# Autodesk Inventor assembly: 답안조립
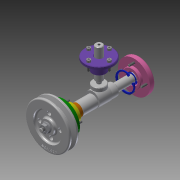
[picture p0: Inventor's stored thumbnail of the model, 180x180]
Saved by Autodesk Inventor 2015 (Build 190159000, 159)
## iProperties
Created: 2020-08
Part Number: 답안조립
Document SubType Name: Assembly
Designer: now
Author: now
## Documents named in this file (18)
- C:\Users\now\Desktop\700806V1042\답안조립.iam
- C:\Users\now\Desktop\700806V1042\Ű 3x3x12.ipt
- C:\Users\now\Desktop\700806V1042\V-벨트풀리.ipt
- C:\Users\now\Desktop\700806V1042\너트 M8.ipt
- C:\Users\now\Desktop\700806V1042\답안본체.ipt
- C:\Users\now\Desktop\700806V1042\뒤커버.ipt
- C:\Users\now\Desktop\700806V1042\멈춤링 15x1.ipt
- C:\Users\now\Desktop\700806V1042\멈춤링 35x1.6.ipt
- 멈춤링 35x1.6.ipt
- C:\Users\now\Desktop\700806V1042\베어링 6202.ipt
- 베어링 6202.ipt
- C:\Users\now\Desktop\700806V1042\볼트 M4.ipt
- C:\Users\now\Desktop\700806V1042\상부커버.ipt
- C:\Users\now\Desktop\700806V1042\슬라이드.ipt
- C:\Users\now\Desktop\700806V1042\앞커버.ipt
- C:\Users\now\Desktop\700806V1042\오일 실 15 30 7.ipt
- C:\Users\now\Desktop\700806V1042\칼라.ipt
- C:\Users\now\Desktop\700806V1042\편심축.ipt
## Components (2 placed, 2 different names)
1. Ű 3x3x12:1 — 각도:1, 각도:2
2. V-벨트풀리:1 — 각도:2
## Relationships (2: Angle 2)
- 각도:1 [Angle]: Ű 3x3x12:1
- 각도:2 [Angle]: Ű 3x3x12:1 ↔ V-벨트풀리:1
